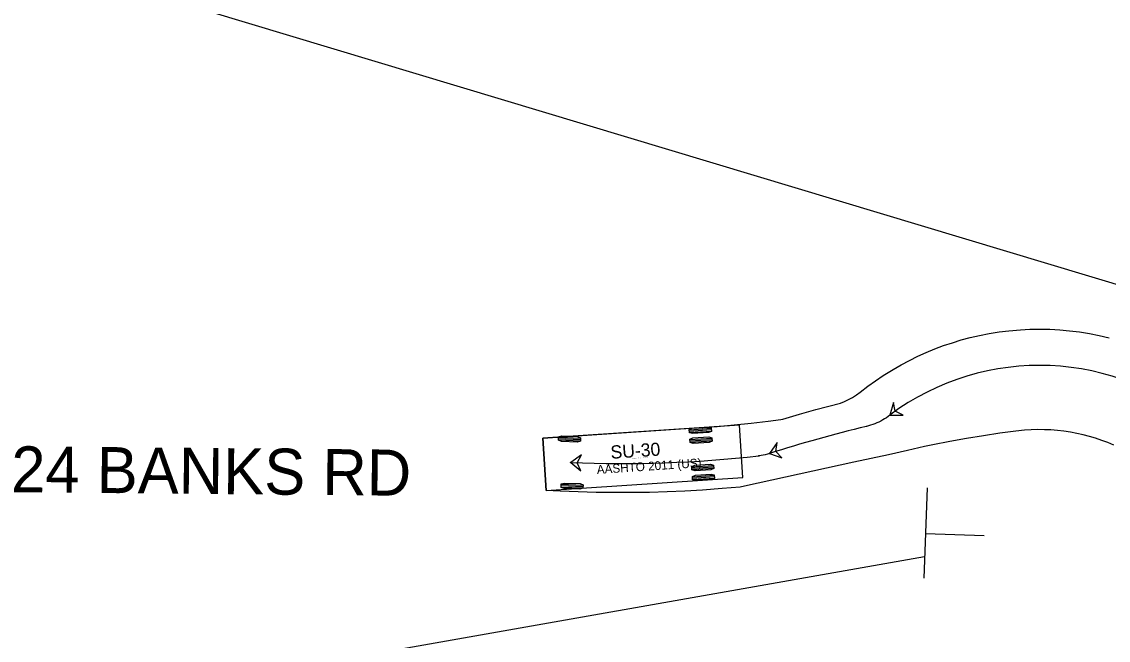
# Model space of a CAD drawing. Extents: x 2096670 to 2098561, y 684033 to 689893.
# Drawn here: x 2097537.1 to 2097702.4, y 686857.7 to 686951.8 of the extents above; entities that cross this region are included whole.
import ezdxf

# ---------------------------------------------------------------- set-up
doc = ezdxf.new("R2010")
doc.units = 0
for name, color, linetype in [('Default', 7, 'Continuous'), ('Old_Level_63', 7, 'Continuous'), ('Prop DSN Text', 7, 'Continuous'), ('Prop Sign E One Way_Right CELL', 7, 'Continuous')]:
    doc.layers.add(name, color=color, linetype=linetype)

msp = doc.modelspace()

# ---------------------------------------------------------------- linework, layer by layer
at = {"layer": 'Old_Level_63'}
for p, q in [((2097646.28, 686890.43), (2097616.35, 686888.45)), ((2097638.65, 686889.72), (2097641.97, 686889.94)), ((2097646.81, 686882.45), (2097646.28, 686890.43)), ((2097616.35, 686888.45), (2097616.88, 686880.47)), ((2097618.74, 686888.16), (2097622.07, 686888.02)), ((2097618.75, 686888.58), (2097622.09, 686888.44)), ((2097618.75, 686888.37), (2097622.08, 686888.23)), ((2097638.66, 686889.51), (2097641.99, 686889.73)), ((2097638.67, 686889.3), (2097642, 686889.52)), ((2097638.74, 686888.22), (2097642.07, 686888.44)), ((2097638.76, 686888.01), (2097642.08, 686888.23)), ((2097638.77, 686887.81), (2097642.1, 686888.03)), ((2097639.02, 686884.06), (2097642.35, 686884.28)), ((2097639.03, 686883.86), (2097642.36, 686884.08)), ((2097639.05, 686883.65), (2097642.37, 686883.87)), ((2097616.88, 686880.47), (2097646.81, 686882.45)), ((2097639.12, 686882.57), (2097642.45, 686882.79)), ((2097639.13, 686882.36), (2097642.46, 686882.58)), ((2097639.15, 686882.15), (2097642.47, 686882.37)), ((2097616.88, 686880.47), (2097616.88, 686880.47)), ((2097619.12, 686881), (2097622.45, 686880.88)), ((2097619.13, 686881.21), (2097622.46, 686881.08)), ((2097619.14, 686881.42), (2097622.47, 686881.29))]:
    msp.add_line(p, q, dxfattribs=at)
for points in [[(2097703.26, 686887.37), (2097702.35, 686887.75), (2097701.42, 686888.1), (2097700.48, 686888.41), (2097699.53, 686888.7), (2097698.57, 686888.95), (2097697.6, 686889.16), (2097696.63, 686889.34), (2097695.64, 686889.49), (2097694.66, 686889.6), (2097693.66, 686889.68), (2097692.67, 686889.72), (2097691.67, 686889.73), (2097690.67, 686889.7), (2097689.65, 686889.64), (2097688.31, 686889.5), (2097685.91, 686889.17), (2097683.39, 686888.78), (2097680.83, 686888.36), (2097678.27, 686887.9), (2097675.7, 686887.41), (2097674.42, 686887.14), (2097671.86, 686886.53), (2097668.94, 686885.88), (2097663.67, 686884.8), (2097647.04, 686881.12), (2097646.36, 686881), (2097643.66, 686880.76), (2097640.63, 686880.54), (2097637.94, 686880.38), (2097635.26, 686880.27), (2097632.59, 686880.19), (2097629.92, 686880.15), (2097627.24, 686880.14), (2097624.48, 686880.18), (2097621.73, 686880.25), (2097618.98, 686880.36), (2097616.88, 686880.47), (2097616.35, 686888.45), (2097637.29, 686889.84), (2097642.87, 686890.22), (2097645.47, 686890.45), (2097648.06, 686890.71), (2097650.64, 686891), (2097652.57, 686891.25), (2097652.89, 686891.32), (2097655.4, 686892.06), (2097657.91, 686892.77), (2097661.67, 686893.78), (2097662.28, 686894.01), (2097662.89, 686894.29), (2097663.49, 686894.62), (2097664.07, 686895), (2097664.65, 686895.43), (2097665.8, 686896.32), (2097666.96, 686897.16), (2097668.15, 686897.96), (2097669.65, 686898.9), (2097670.88, 686899.6), (2097672.13, 686900.27), (2097673.41, 686900.89), (2097674.7, 686901.48), (2097676.01, 686902.01), (2097677.33, 686902.51), (2097678.67, 686902.96), (2097680.02, 686903.37), (2097681.39, 686903.73), (2097682.81, 686904.06), (2097684.28, 686904.35), (2097685.78, 686904.59), (2097687.26, 686904.78), (2097689.03, 686904.93), (2097690.47, 686905), (2097691.98, 686905.03), (2097693.5, 686905), (2097695.02, 686904.92), (2097696.51, 686904.78), (2097698.03, 686904.6), (2097699.53, 686904.36), (2097701.03, 686904.06), (2097702.52, 686903.72)], [(2097669.18, 686891.94), (2097671.18, 686891.92), (2097669.98, 686892.54), (2097669.72, 686893.87), (2097669.18, 686891.94)], [(2097669.18, 686891.94), (2097668.91, 686891.74), (2097668.64, 686891.55), (2097668.36, 686891.37), (2097668.07, 686891.2), (2097667.78, 686891.04), (2097667.48, 686890.89), (2097667.18, 686890.75), (2097666.87, 686890.62), (2097666.56, 686890.51), (2097666.24, 686890.4), (2097665.92, 686890.31), (2097665.6, 686890.23)], [(2097650.85, 686886.11), (2097652.73, 686885.43), (2097651.8, 686886.41), (2097652, 686887.75), (2097650.85, 686886.11)], [(2097620.6, 686884.72), (2097622.14, 686883.44), (2097621.6, 686884.68), (2097622.24, 686885.88), (2097620.6, 686884.72)], [(2097650.85, 686886.11), (2097650.53, 686886.01), (2097650.21, 686885.92), (2097649.89, 686885.85), (2097649.56, 686885.78), (2097649.23, 686885.74)]]:
    msp.add_lwpolyline(points, dxfattribs=at)
for points in [[(2097669.18, 686891.94), (2097671.18, 686891.92), (2097669.98, 686892.54), (2097669.72, 686893.87)], [(2097638.68, 686889.25), (2097638.64, 686889.77), (2097639.1, 686889.96), (2097641.49, 686890.12), (2097641.97, 686889.99), (2097642, 686889.47), (2097641.55, 686889.28), (2097639.15, 686889.13)], [(2097618.74, 686888.11), (2097618.76, 686888.63), (2097619.23, 686888.77), (2097621.63, 686888.67), (2097622.09, 686888.49), (2097622.07, 686887.97), (2097621.59, 686887.83), (2097619.19, 686887.93)], [(2097638.78, 686887.75), (2097638.74, 686888.27), (2097639.2, 686888.46), (2097641.59, 686888.62), (2097642.07, 686888.49), (2097642.1, 686887.97), (2097641.65, 686887.79), (2097639.25, 686887.63)], [(2097650.85, 686886.11), (2097652.73, 686885.43), (2097651.8, 686886.41), (2097652, 686887.75)], [(2097620.6, 686884.72), (2097622.14, 686883.44), (2097621.6, 686884.68), (2097622.24, 686885.88)], [(2097639.05, 686883.6), (2097639.02, 686884.12), (2097639.47, 686884.3), (2097641.87, 686884.46), (2097642.34, 686884.34), (2097642.38, 686883.82), (2097641.92, 686883.63), (2097639.53, 686883.47)], [(2097619.12, 686880.95), (2097619.14, 686881.47), (2097619.61, 686881.61), (2097622.01, 686881.52), (2097622.47, 686881.34), (2097622.45, 686880.82), (2097621.98, 686880.69), (2097619.58, 686880.78)], [(2097639.15, 686882.1), (2097639.12, 686882.62), (2097639.57, 686882.81), (2097641.97, 686882.96), (2097642.44, 686882.84), (2097642.48, 686882.32), (2097642.02, 686882.13), (2097639.63, 686881.97)]]:
    msp.add_lwpolyline(points, close=True, dxfattribs=at)
for centre in [(2097669.18, 686891.94), (2097669.18, 686891.94), (2097665.6, 686890.23), (2097665.6, 686890.23), (2097649.23, 686885.74), (2097649.23, 686885.74), (2097650.85, 686886.11), (2097650.85, 686886.11), (2097620.6, 686884.72)]:
    msp.add_circle(centre, 0.0417, dxfattribs=at)
for centre, radius, start, end in [((2097691.92, 686861.49), 38.01, 48.3146, 126.7544), ((2097717.21, 686677.13), 219.26, 103.6148, 107.6173), ((2097628.19, 687075.03), 190.46, 267.7172, 276.3426)]:
    msp.add_arc(centre, radius, start, end, dxfattribs=at)
at = {"layer": 'Prop DSN Text'}
for p, q in [((2097674.82, 686880.89), (2097674.33, 686867.12)), ((2097674.57, 686873.95), (2097683.49, 686873.63))]:
    msp.add_line(p, q, dxfattribs=at)
at = {"layer": 'Prop Sign E One Way_Right CELL'}
for p, q in [((2097544.37, 686959.78), (2097716.41, 686908.02)), ((2097361.08, 686815.27), (2097674.44, 686870.42))]:
    msp.add_line(p, q, dxfattribs=at)

# ---------------------------------------------------------------- texts
at = {"layer": 'Default'}
msp.add_text('-Y2- SR 2724 BANKS RD', height=7, rotation=359.4886, dxfattribs=at).set_placement((2097489.13, 686880.62))
at = {"layer": 'Old_Level_63'}
for s, height, p in [('SU-30', 2, (2097626.72, 686885.29)), ('AASHTO 2011 (US)', 1.3333, (2097624.61, 686882.98)), ('(c) 2022 Transoft Solutions, Inc. All rights reserved.', 0.08, (2097629.95, 686885.3))]:
    msp.add_text(s, height=height, rotation=3.7862, dxfattribs=at).set_placement(p)

doc.saveas('drawing.dxf')
